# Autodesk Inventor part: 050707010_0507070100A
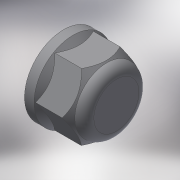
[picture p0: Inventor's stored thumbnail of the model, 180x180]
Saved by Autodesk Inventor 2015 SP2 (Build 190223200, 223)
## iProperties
Created: 2017-05
Part Number: 050707010_0507070100A
Material: Generic
Description: PLASSON CAP 1"
Document SubType Name: Modeling
Designer: KIM
Density: 1 g/cm^3
Appearance: Default
Author: KIM
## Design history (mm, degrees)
derived "050707.ipt"
feature "Solid1::050707.ipt"
tag "TaggingFeature1"
body "Solid1"
other parameters: "d0" = 32, "d1" = 1.9, "d2" = 30.291, "d3" = 19, "d4" = 1.9, "d5" = 135 deg, "d6" = 33.3201, "d8" = 42.5, "d9" = 41, "d10" = 135 deg, "d11" = 5.7, "d13" = 5.7, "d16" = 0, "Rp_" = 30.291, "H_" = 32, "l_2" = 19
